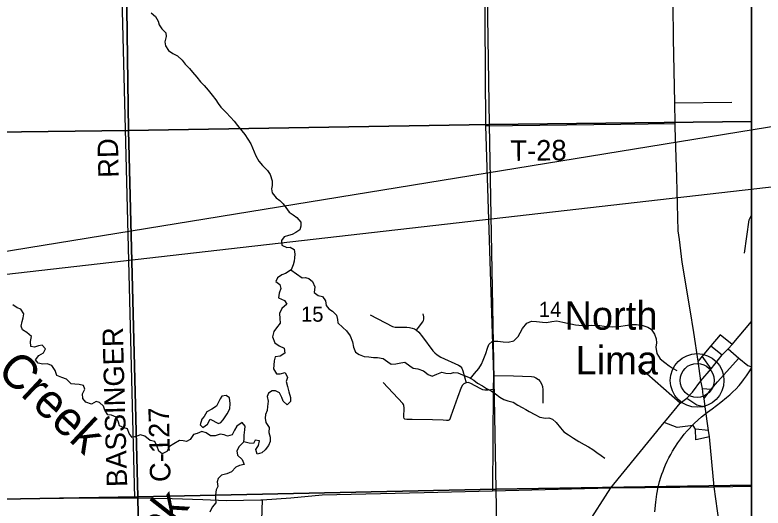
# Model space of a CAD drawing. Extents: x 0 to 36.9, y 0 to 22.
# Drawn here: x 6.858 to 8.932, y 17.496 to 18.864 of the extents above; entities that cross this region are included whole.
import ezdxf

# ---------------------------------------------------------------- set-up
doc = ezdxf.new("R2010")
doc.units = 0
for name, color, linetype in [('Default', 7, 'Continuous'), ('GM_X_County_Road', 7, 'Continuous'), ('GM_X_County_Road_Text', 7, 'Continuous'), ('GM_X_Major_River', 7, 'Continuous'), ('GM_X_Major_River_Text', 7, 'Continuous'), ('GM_X_Minor_Lake', 7, 'Continuous'), ('GM_X_Minor_River', 7, 'Continuous'), ('GM_X_Minor_River_Text', 7, 'Continuous'), ('GM_X_Rail_Line', 7, 'Continuous'), ('GM_X_Section', 7, 'Continuous'), ('GM_X_Section_Text', 7, 'Continuous'), ('GM_X_State_Route', 7, 'Continuous'), ('GM_X_Township_Road', 7, 'Continuous'), ('GM_X_Township_Road_Text', 7, 'Continuous'), ('GM_X_Unincorporated', 7, 'Continuous'), ('GM_X_Unincorporated_Location', 7, 'Continuous'), ('GM_X_Unincorporated_Text', 7, 'Continuous'), ('SH_Cut_Line', 7, 'Continuous'), ('SH_Data', 7, 'Continuous'), ('SH_Text', 7, 'Continuous')]:
    doc.layers.add(name, color=color, linetype=linetype)

msp = doc.modelspace()

# ---------------------------------------------------------------- linework, layer by layer
at = {"layer": 'Default'}
for points in [[(8.9, 18.5682), (8.9, 19.5814), (8.157, 19.5752), (8.1724, 18.5598)], [(8.9, 17.5601), (8.9, 18.5682), (8.1724, 18.5598), (8.1912, 17.5487)], [(8.9, 16.5477), (8.9, 17.5601), (8.1912, 17.5487), (8.21, 16.5368)]]:
    msp.add_lwpolyline(points, close=True, dxfattribs=at)
at = {"layer": 'GM_X_County_Road'}
msp.add_line((7.1903, 17.5251), (7.1513, 19.0425), dxfattribs=at)
for points in [[(8.1566, 19.6762), (8.1561, 19.5805), (8.1626, 18.5567), (8.1844, 17.8641), (8.1842, 17.825), (8.1824, 17.5445)], [(7.5431, 17.5191), (7.5334, 17.2126), (7.5226, 16.9418), (7.5085, 16.6619), (7.5038, 16.5816), (7.5026, 16.5512), (7.5032, 16.5386), (7.5044, 16.52), (7.56, 16.4312), (7.6351, 16.3326)]]:
    msp.add_lwpolyline(points, dxfattribs=at)
at = {"layer": 'GM_X_Major_River'}
for points in [[(7.2351, 18.8695), (7.2474, 18.8599), (7.2545, 18.8471), (7.2577, 18.8365), (7.2651, 18.8256)], [(7.2651, 18.8256), (7.2763, 18.8148), (7.2772, 18.8046), (7.2733, 18.7897), (7.2754, 18.7784), (7.284, 18.7652), (7.2956, 18.7571), (7.3086, 18.7505), (7.3217, 18.7386), (7.3299, 18.7277), (7.3419, 18.715), (7.3497, 18.7049), (7.3624, 18.6911), (7.3722, 18.6784), (7.3822, 18.6683), (7.3931, 18.6556), (7.4051, 18.6418), (7.4144, 18.6283), (7.4211, 18.6181), (7.4285, 18.6084), (7.4439, 18.5931), (7.4555, 18.5808), (7.4652, 18.5692), (7.4749, 18.5572), (7.4866, 18.543), (7.4951, 18.5322), (7.5037, 18.5194), (7.5115, 18.5067), (7.5167, 18.495), (7.5211, 18.4848), (7.5262, 18.4735), (7.5337, 18.4588), (7.5445, 18.4465), (7.5584, 18.4323), (7.5651, 18.4218), (7.5711, 18.4041), (7.571, 18.3912), (7.5689, 18.3813), (7.5706, 18.3703), (7.5818, 18.3572), (7.5922, 18.349), (7.6019, 18.3397), (7.6089, 18.3296), (7.6186, 18.3173), (7.629, 18.3095), (7.6398, 18.3021), (7.6502, 18.289), (7.6508, 18.278), (7.648, 18.2684), (7.6371, 18.2603), (7.6269, 18.2555), (7.6167, 18.2523), (7.6039, 18.2483), (7.5965, 18.2383), (7.5978, 18.2258), (7.6116, 18.2192), (7.6211, 18.2201), (7.6318, 18.2138), (7.6336, 18.2006), (7.6334, 18.1907), (7.6317, 18.1808), (7.6296, 18.1713), (7.6234, 18.1575), (7.6076, 18.1473), (7.5974, 18.143), (7.5858, 18.1352), (7.5814, 18.1245), (7.5926, 18.1167), (7.5947, 18.1053), (7.59, 18.092), (7.5883, 18.0794), (7.6051, 18.0717), (7.6114, 18.062), (7.5979, 18.0496), (7.5914, 18.0362), (7.5924, 18.0225), (7.593, 18.0096), (7.5833, 17.9962), (7.5759, 17.9862), (7.5716, 17.9709), (7.5784, 17.9551), (7.5907, 17.9462), (7.6041, 17.94), (7.6066, 17.926), (7.5935, 17.9181), (7.5791, 17.9156), (7.5762, 17.9045), (7.5761, 17.8924), (7.5751, 17.8825), (7.5833, 17.869), (7.5936, 17.8684), (7.6072, 17.8724), (7.6135, 17.8585), (7.6095, 17.8478), (7.6132, 17.8331), (7.6173, 17.8191), (7.6221, 17.8032), (7.6223, 17.7918), (7.6122, 17.7829), (7.6014, 17.793), (7.5982, 17.8032)], [(7.5982, 17.8032), (7.5911, 17.8156), (7.5804, 17.8215), (7.5709, 17.8217), (7.5611, 17.815), (7.5575, 17.8055), (7.5604, 17.7926), (7.558, 17.7785), (7.5571, 17.7668), (7.5527, 17.7557), (7.5514, 17.7461), (7.5535, 17.734), (7.5628, 17.7202), (7.562, 17.7061), (7.5652, 17.6929), (7.5658, 17.6811), (7.5611, 17.6696), (7.5518, 17.6581), (7.5421, 17.6495), (7.5296, 17.6463), (7.5256, 17.6584), (7.533, 17.6695), (7.5362, 17.6832), (7.5236, 17.6849), (7.5192, 17.6753), (7.507, 17.6762), (7.4925, 17.6802), (7.4791, 17.667), (7.4732, 17.6555), (7.4746, 17.643), (7.4874, 17.6311), (7.4933, 17.6171), (7.4801, 17.6142), (7.4703, 17.6099), (7.4584, 17.5968), (7.4452, 17.5916), (7.4308, 17.5879), (7.4211, 17.5786), (7.4186, 17.5687), (7.42, 17.5562), (7.416, 17.5466), (7.4136, 17.5329), (7.4137, 17.5223), (7.4147, 17.5113), (7.4051, 17.4986), (7.3981, 17.4848)]]:
    msp.add_lwpolyline(points, dxfattribs=at)
at = {"layer": 'GM_X_Minor_Lake'}
msp.add_line((8.8938, 18.2958), (8.9, 18.3083), dxfattribs=at)
for points in [[(8.8805, 18.2036), (8.8938, 18.2958)], [(7.4459, 17.7575), (7.4536, 17.772), (7.4545, 17.7861), (7.4528, 17.8017), (7.4431, 17.8083), (7.4314, 17.807), (7.4266, 17.7997), (7.4166, 17.7794), (7.4035, 17.7705), (7.3895, 17.7634), (7.3825, 17.7507), (7.3758, 17.7434), (7.3715, 17.727), (7.3792, 17.7195), (7.392, 17.7289), (7.399, 17.7434), (7.4223, 17.7309)], [(7.4223, 17.7309), (7.4286, 17.7336), (7.4352, 17.7408), (7.4459, 17.7575)]]:
    msp.add_lwpolyline(points, dxfattribs=at)
at = {"layer": 'GM_X_Minor_River'}
for points in [[(7.6231, 18.1574), (7.6538, 18.1353), (7.6632, 18.1358), (7.6728, 18.133), (7.6828, 18.1244), (7.6895, 18.1101), (7.6879, 18.0945), (7.6983, 18.0856), (7.7105, 18.0831), (7.7187, 18.0708), (7.7208, 18.0586), (7.7282, 18.0485), (7.7386, 18.0423), (7.7498, 18.0311), (7.7523, 18.0197), (7.7536, 18.0099), (7.7671, 17.9972), (7.7771, 17.9879), (7.7869, 17.974), (7.7936, 17.9578), (7.7966, 17.9423), (7.8021, 17.9284), (7.8125, 17.9225), (7.8263, 17.9163), (7.8388, 17.9161), (7.8518, 17.9137), (7.8635, 17.9143), (7.8788, 17.9115), (7.8915, 17.9023), (7.9011, 17.8956), (7.9136, 17.8962), (7.9283, 17.8991), (7.9389, 17.9012), (7.9528, 17.8912), (7.9624, 17.8846), (7.9754, 17.8825), (7.9903, 17.8771), (8.0041, 17.8667), (8.0144, 17.8623), (8.0276, 17.8679), (8.0412, 17.8734), (8.0527, 17.8702), (8.0644, 17.8693), (8.075, 17.8722), (8.086, 17.8716), (8.0991, 17.8661), (8.1155, 17.8592), (8.1301, 17.8507), (8.1409, 17.8426), (8.1539, 17.8352), (8.1658, 17.8282), (8.1788, 17.8212), (8.1908, 17.8135), (8.2023, 17.8038), (8.2138, 17.7972), (8.2245, 17.794), (8.2394, 17.7897), (8.2525, 17.7816), (8.264, 17.7749), (8.2743, 17.7694), (8.2839, 17.7643), (8.2992, 17.7558), (8.3134, 17.7489), (8.3287, 17.7457), (8.3382, 17.7463), (8.3485, 17.743), (8.3585, 17.7337), (8.3709, 17.7191), (8.3802, 17.7079), (8.3929, 17.6994), (8.4064, 17.6905), (8.4217, 17.6806), (8.4363, 17.6728), (8.4482, 17.6662), (8.4601, 17.6585), (8.4712, 17.6507), (8.4832, 17.6422), (8.4932, 17.6344)], [(7.4925, 17.6802), (7.4932, 17.6885), (7.493, 17.6988), (7.4954, 17.7132), (7.4963, 17.7231), (7.4874, 17.7336), (7.4728, 17.7235), (7.4665, 17.7123), (7.4603, 17.6997), (7.4475, 17.6961), (7.4375, 17.6997), (7.4265, 17.701), (7.4133, 17.6966), (7.4004, 17.6967), (7.3881, 17.7049), (7.3758, 17.7088), (7.3626, 17.7033), (7.3528, 17.7004), (7.3436, 17.6866), (7.3334, 17.6807), (7.3239, 17.6832), (7.314, 17.6838), (7.2986, 17.6744), (7.2862, 17.6669), (7.2792, 17.6535), (7.2664, 17.6472), (7.2568, 17.6546), (7.2517, 17.6671), (7.2453, 17.6806), (7.2324, 17.6842), (7.2181, 17.6957), (7.2063, 17.6997), (7.1953, 17.6961), (7.1825, 17.6924), (7.1747, 17.7029), (7.1703, 17.7157), (7.1607, 17.719), (7.1473, 17.7244), (7.1445, 17.7342), (7.1386, 17.7482), (7.1255, 17.7537), (7.1149, 17.7554), (7.1067, 17.7681), (7.1031, 17.7791), (7.0926, 17.7891), (7.0831, 17.792), (7.0696, 17.7842), (7.0539, 17.7903), (7.0461, 17.8004), (7.0451, 17.8133), (7.0513, 17.826), (7.0481, 17.8362), (7.0355, 17.8394), (7.0234, 17.8403), (7.0139, 17.8412), (7.0011, 17.8539), (6.9881, 17.8586), (6.9743, 17.8644), (6.9691, 17.8776), (6.9598, 17.8919), (6.9475, 17.8966), (6.935, 17.8956), (6.9221, 17.898), (6.9147, 17.9078), (6.9236, 17.9197), (6.9367, 17.9268), (6.9426, 17.9383), (6.9329, 17.948), (6.9231, 17.9463), (6.9118, 17.943), (6.9022, 17.9448), (6.9009, 17.9588), (6.904, 17.9725), (6.8909, 17.9833), (6.879, 17.991), (6.8747, 18.0008), (6.8775, 18.0142), (6.8807, 18.0237), (6.8828, 18.0348), (6.8738, 18.0479), (6.8642, 18.0519), (6.8523, 18.06)], [(8.1213, 17.8559), (8.1324, 17.8698), (8.1439, 17.8836), (8.1517, 17.8952), (8.1564, 17.9063), (8.1637, 17.925), (8.1684, 17.9395), (8.1716, 17.9498), (8.1821, 17.9591), (8.1969, 17.9594), (8.2121, 17.957), (8.2258, 17.9569), (8.2409, 17.9606), (8.2536, 17.9726), (8.2591, 17.9825), (8.265, 17.9948), (8.2772, 18.0094), (8.2901, 18.0146), (8.3045, 18.0137), (8.3212, 18.0121), (8.3315, 18.0108), (8.3463, 18.0141), (8.3607, 18.0155), (8.3771, 18.0124), (8.39, 18.0096), (8.3995, 18.0075), (8.4125, 18.0047), (8.4304, 18.0023), (8.4422, 18.0022), (8.4566, 18.0032), (8.4691, 18.003), (8.4801, 18.0025), (8.4915, 18.0011), (8.5011, 18.0002), (8.514, 17.9993), (8.5254, 17.9995), (8.5383, 18.0008), (8.5504, 18.003), (8.5686, 18.0056), (8.5818, 18.0054), (8.599, 18.0027), (8.6127, 17.998), (8.6223, 17.9925), (8.6309, 17.979), (8.6357, 17.9654), (8.6367, 17.9548), (8.6354, 17.9422), (8.638, 17.9252), (8.6473, 17.9105), (8.6604, 17.9001), (8.6724, 17.8909), (8.6831, 17.8831), (8.6931, 17.8776)]]:
    msp.add_lwpolyline(points, dxfattribs=at)
at = {"layer": 'GM_X_Rail_Line'}
for points in [[(8.9, 14.5158), (8.9, 20.5927), (8.7004, 20.5894), (8.4791, 20.5781), (8.4706, 20.5777), (8.1451, 20.581), (7.7514, 20.5725), (7.4889, 20.5693), (7.1656, 20.5637), (7.1468, 20.5633), (6.1727, 20.5478), (5.9236, 20.5446), (5.3186, 20.5329), (5.2978, 20.5324), (5.1496, 20.5295), (4.5929, 20.5183), (4.1742, 20.5119), (4.2095, 19.5156), (4.2124, 19.4314), (4.22, 18.531), (4.2174, 18.4382), (4.2214, 17.442), (4.2237, 16.806), (4.2428, 16.065)], [(8.6324, 17.4861), (8.6346, 17.5126), (8.6374, 17.5346), (8.6415, 17.5543), (8.6455, 17.5705), (8.6491, 17.5822), (8.652, 17.5907), (8.655, 17.5991), (8.6583, 17.6075), (8.6622, 17.6166), (8.6664, 17.6261), (8.6714, 17.6359), (8.6762, 17.6452), (8.6811, 17.6539), (8.6879, 17.6644), (8.6959, 17.6769), (8.7046, 17.6883), (8.7138, 17.7009), (8.7221, 17.7109), (8.7415, 17.7312), (8.7522, 17.7409), (8.7614, 17.7491), (8.7701, 17.7558), (8.7785, 17.7625), (8.791, 17.7713), (8.8149, 17.7903), (8.8309, 17.8027), (8.8402, 17.8105), (8.8489, 17.8186), (8.8569, 17.8262), (8.8658, 17.836), (8.8737, 17.8457), (8.8783, 17.8516), (8.8869, 17.8634), (8.8936, 17.8739), (8.9, 17.8847)]]:
    msp.add_lwpolyline(points, dxfattribs=at)
at = {"layer": 'GM_X_Section'}
for points in [[(8.157, 19.5752), (8.1724, 18.5598), (7.173, 18.5435), (7.1591, 19.5574)], [(7.1591, 19.5574), (7.173, 18.5435), (6.2072, 18.5313), (6.1867, 19.5319)], [(7.173, 18.5435), (8.1724, 18.5598), (8.1912, 17.5487), (7.1983, 17.5272)], [(6.2072, 18.5313), (7.173, 18.5435), (7.1983, 17.5272), (6.2201, 17.5106)], [(8.1912, 17.5487), (8.21, 16.5368), (7.2171, 16.5161), (7.1983, 17.5272)], [(7.1983, 17.5272), (7.2171, 16.5161), (6.226, 16.4996), (6.2201, 17.5106)]]:
    msp.add_lwpolyline(points, close=True, dxfattribs=at)
at = {"layer": 'GM_X_State_Route'}
for p, q in [((8.3041, 17.2334), (8.5106, 17.5524)), ((8.5106, 17.5524), (8.797, 17.5552)), ((8.797, 17.5552), (8.9, 17.5574))]:
    msp.add_line(p, q, dxfattribs=at)
for points in [[(8.689, 18.5531), (8.6887, 18.5631), (8.688, 18.62), (8.6839, 18.799), (8.6827, 18.8932), (8.6814, 18.9339)], [(8.7003, 18.2415), (8.6973, 18.2654), (8.6931, 18.4132), (8.689, 18.5531)], [(8.7402, 17.9832), (8.7302, 18.046), (8.7083, 18.1787), (8.7003, 18.2415)], [(8.8277, 17.9294), (8.8359, 17.9377), (8.8463, 17.9504), (8.9, 18.0137)], [(8.7645, 17.8279), (8.76, 17.849), (8.7528, 17.9035), (8.7402, 17.9832)], [(8.76, 17.849), (8.7887, 17.8828), (8.8194, 17.9212), (8.8277, 17.9294)], [(8.6649, 17.7414), (8.7026, 17.7876), (8.7214, 17.8014), (8.7366, 17.8176), (8.76, 17.849)], [(8.797, 17.5552), (8.7835, 17.6937), (8.7807, 17.7113), (8.7721, 17.7776), (8.7693, 17.8003), (8.7662, 17.8093), (8.7645, 17.8279)], [(8.5106, 17.5524), (8.6586, 17.7337), (8.6649, 17.7414)], [(7.9925, 17.54), (8.1824, 17.5445), (8.5106, 17.5524)], [(8.8585, 17.3657), (8.823, 17.4109), (8.8158, 17.4263), (8.8103, 17.4551), (8.797, 17.5552)], [(7.0911, 17.5244), (7.1903, 17.5251), (7.2938, 17.5227), (7.3791, 17.5206), (7.4432, 17.5173), (7.5398, 17.5189), (7.5431, 17.5191), (7.623, 17.5247), (7.7096, 17.5333), (7.9925, 17.54)], [(6.4333, 17.5154), (6.6618, 17.5193), (6.7082, 17.5202), (6.7526, 17.5212), (6.7935, 17.5224), (7.0911, 17.5244)]]:
    msp.add_lwpolyline(points, dxfattribs=at)
at = {"layer": 'GM_X_Township_Road'}
for p, q in [((8.688, 18.62), (8.8461, 18.6221)), ((8.1626, 18.5567), (8.6887, 18.5631)), ((8.7873, 17.9463), (8.8194, 17.9212)), ((8.7887, 17.8828), (8.7631, 17.9173)), ((8.8064, 17.8465), (8.8649, 17.9125)), ((8.7026, 17.7876), (8.5867, 17.8889)), ((8.7645, 17.8279), (8.7882, 17.8262))]:
    msp.add_line(p, q, dxfattribs=at)
for points in [[(7.8429, 18.0321), (7.9047, 18.0003), (7.9083, 17.9987), (7.9118, 17.9978), (7.9198, 17.9978), (7.9446, 17.9977), (7.9521, 17.9971), (7.9589, 17.9957), (7.9657, 17.9933), (7.9717, 17.9901), (7.9778, 17.9845), (7.9877, 17.9716), (8.017, 17.9322), (8.0222, 17.9268), (8.0284, 17.9213), (8.0392, 17.9147), (8.0876, 17.8927), (8.0922, 17.8898), (8.0969, 17.8843), (8.1001, 17.8769), (8.1093, 17.8434)], [(7.9717, 17.9901), (7.977, 17.997), (7.9888, 18.0126), (7.9906, 18.0163), (7.9919, 18.0205), (7.9917, 18.0268), (7.9901, 18.035)], [(8.8463, 17.9504), (8.8135, 17.9766), (8.7873, 17.9463), (8.7631, 17.9173), (8.7528, 17.9035)], [(8.8359, 17.9377), (8.8649, 17.9125), (8.8901, 17.8918), (8.9, 17.8884)], [(8.1844, 17.8641), (8.2401, 17.8628), (8.2902, 17.8614), (8.2966, 17.8601), (8.302, 17.8574), (8.3095, 17.8527), (8.3144, 17.8476), (8.3182, 17.841), (8.321, 17.8337), (8.3214, 17.8241), (8.3218, 17.787)], [(8.1842, 17.825), (8.17, 17.8236), (8.161, 17.8237), (8.1553, 17.8247), (8.1516, 17.826), (8.1477, 17.8279), (8.1221, 17.8419), (8.1176, 17.8437), (8.1148, 17.8442), (8.1093, 17.8434), (8.1023, 17.8406), (8.0987, 17.8369), (8.0954, 17.8312), (8.0851, 17.8032), (8.0665, 17.7513), (8.0648, 17.7458), (8.0625, 17.7414), (8.059, 17.7391), (8.0542, 17.7396), (8.0452, 17.7405), (8.016, 17.7411), (7.959, 17.7422), (7.9445, 17.7419), (7.9392, 17.7429), (7.9373, 17.745), (7.9358, 17.7483), (7.9374, 17.7748), (7.9364, 17.7805), (7.935, 17.7838), (7.933, 17.7866), (7.8789, 17.8444)], [(8.7693, 17.8003), (8.7882, 17.8262), (8.7895, 17.8275), (8.8064, 17.8465)], [(8.7214, 17.8014), (8.7487, 17.7831), (8.7721, 17.7776)], [(8.7807, 17.7113), (8.7451, 17.7152), (8.7388, 17.7251), (8.6945, 17.7195), (8.6586, 17.7337)], [(8.7835, 17.6937), (8.7462, 17.6856), (8.7451, 17.7152)]]:
    msp.add_lwpolyline(points, dxfattribs=at)
at = {"layer": 'GM_X_Unincorporated'}
for radius in [0.0744, 0.0472]:
    msp.add_circle((8.7496, 17.8504), radius, dxfattribs=at)
at = {"layer": 'GM_X_Unincorporated_Location'}
msp.add_line((8.7496, 17.8504), (8.7496, 17.8504), dxfattribs=at)
at = {"layer": 'SH_Cut_Line'}
msp.add_lwpolyline([(8.9, 14.5158), (8.9, 20.9), (2.1, 20.9), (2.1, 14.4405)], dxfattribs=at)
at = {"layer": 'SH_Data'}
msp.add_line((8.9, 20.9), (8.9, 14.1), dxfattribs=at)
at = {"layer": 'SH_Text'}
msp.add_lwpolyline([(5.5389, 17.9969), (9.1094, 18.4044), (9.1094, 18.5783)], close=True, dxfattribs=at)

# ---------------------------------------------------------------- texts
at = {"layer": 'GM_X_County_Road_Text'}
for s, rotation, p in [('RD', 91.4806, (7.1459, 18.413)), ('BASSINGER', 91.6084, (7.1692, 17.5555)), ('C-127', 91.3773, (7.2894, 17.5693))]:
    msp.add_text(s, height=0.05682, rotation=rotation, dxfattribs=at).set_placement(p)
at = {"layer": 'GM_X_Major_River_Text'}
msp.add_text('Creek', height=0.09474, rotation=51.8533, dxfattribs=at).set_placement((7.1348, 17.2339))
at = {"layer": 'GM_X_Minor_River_Text'}
msp.add_text('Creek', height=0.09474, rotation=316.7828, dxfattribs=at).set_placement((6.8044, 17.8722))
at = {"layer": 'GM_X_Section_Text'}
for s, p in [('15', (7.6511, 18.0133)), ('14', (8.3107, 18.0265))]:
    msp.add_text(s, height=0.04186, rotation=0, dxfattribs=at).set_placement(p)
at = {"layer": 'GM_X_Township_Road_Text'}
msp.add_text('T-28', height=0.05682, rotation=0.7069, dxfattribs=at).set_placement((8.2319, 18.4591))
at = {"layer": 'GM_X_Unincorporated_Text'}
for s, p in [('North', (8.3815, 17.991)), ('Lima', (8.4124, 17.8669))]:
    msp.add_text(s, height=0.07898, rotation=0, dxfattribs=at).set_placement(p)

doc.saveas('drawing.dxf')
